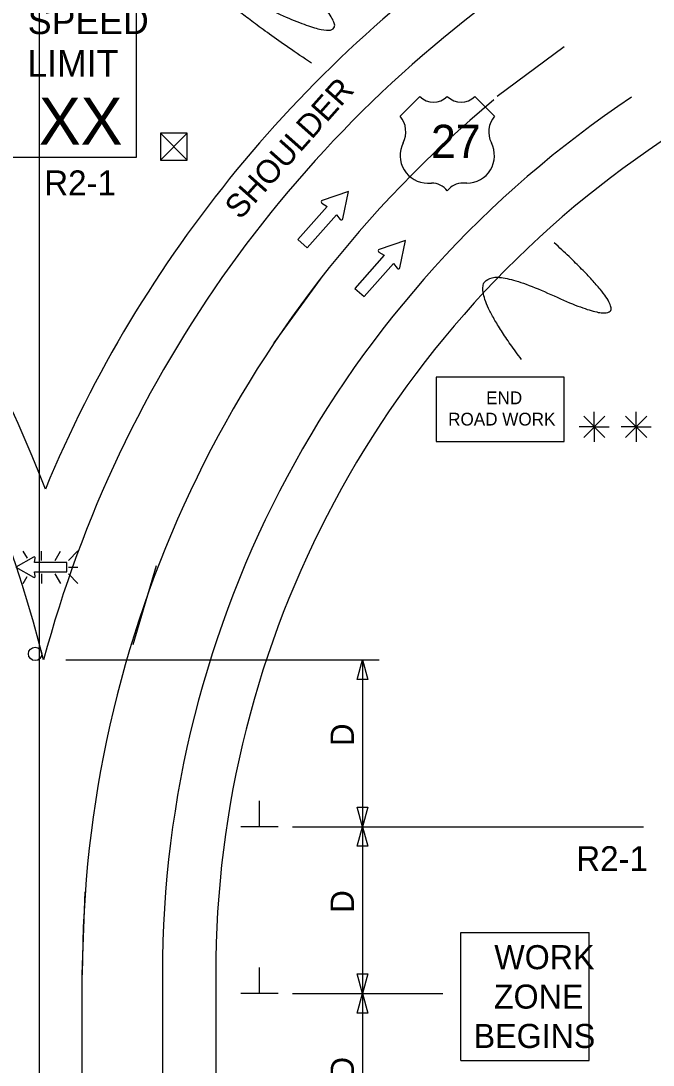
# Model space of a CAD drawing. Extents: x 16303 to 18479, y 5704 to 6974.
# Drawn here: x 16999.2 to 17188.8, y 6497.9 to 6811 of the extents above; entities that cross this region are included whole.
import ezdxf

# ---------------------------------------------------------------- set-up
doc = ezdxf.new("R2010")
doc.units = 0
for name, color, linetype in [('ALI_LEGAL_EX', 7, 'Continuous'), ('MT_SCRATCH_LEVEL_E', 7, 'Continuous'), ('PAVT_EDGE_EX', 7, 'Continuous'), ('TRAFFIC_SIGNS_PR', 7, 'Continuous'), ('TYPICAL_EX', 7, 'Continuous'), ('TYPICAL_TEXT_DIMEN_PR', 7, 'Continuous')]:
    doc.layers.add(name, color=color, linetype=linetype)

msp = doc.modelspace()

# ---------------------------------------------------------------- linework, layer by layer
at = {"layer": 'ALI_LEGAL_EX'}
for p, q in [((17004.68, 6974.12), (17004.68, 6155.98)), ((17004.68, 6877.04), (17004.68, 6013.12)), ((17039.84, 6647.53), (17032.85, 6623.88)), ((17017.65, 6024.8), (17017.65, 6525.15))]:
    msp.add_line(p, q, dxfattribs=at)
for points in [[(17142.04, 6788.34), (17162.08, 6803.27)], [(17075.14, 6714.42), (17089.89, 6734.61)], [(17017.7, 6524.8), (17017.65, 6525.15), (17018.48, 6549.78)]]:
    msp.add_lwpolyline(points, dxfattribs=at)
msp.add_arc((17357.65, 6525.15), 340, 129.5666, 180, dxfattribs=at)
at = {"layer": 'MT_SCRATCH_LEVEL_E'}
for p, q in [((17097.48, 6759.79), (17089.6, 6757.11)), ((17095.77, 6751.62), (17097.48, 6759.79)), ((17091.04, 6755.33), (17082.24, 6745.42)), ((17089.5, 6756.28), (17091.04, 6755.33)), ((17085.03, 6742.93), (17093.84, 6752.84)), ((17093.84, 6752.84), (17094.96, 6751.43)), ((17082.24, 6745.42), (17085.03, 6742.93)), ((17114.56, 6745.13), (17106.68, 6742.45)), ((17112.85, 6736.96), (17114.56, 6745.13)), ((17106.59, 6741.62), (17108.12, 6740.67)), ((17108.12, 6740.67), (17099.32, 6730.76)), ((17102.12, 6728.28), (17110.92, 6738.19)), ((17110.92, 6738.19), (17112.04, 6736.77)), ((17099.32, 6730.76), (17102.12, 6728.28))]:
    msp.add_line(p, q, dxfattribs=at)
for centre, start, end in [((17089.75, 6756.67), 108.8028, 238.3418), ((17095.31, 6751.73), 218.4141, 348.1511), ((17106.84, 6742.01), 108.8028, 238.3418), ((17112.4, 6737.07), 218.4141, 348.1511)]:
    msp.add_arc(centre, 0.463, start, end, dxfattribs=at)
at = {"layer": 'PAVT_EDGE_EX'}
for p, q in [((17041.65, 6525.15), (17041.65, 6062.71)), ((17057.65, 6525.15), (17057.65, 6062.71))]:
    msp.add_line(p, q, dxfattribs=at)
for centre, radius, start, end in [((16629.65, 6525.15), 404, 21.0961, 68.7791), ((16629.65, 6525.15), 388, 14.0482, 68.7791), ((17357.65, 6525.15), 380, 123.6935, 157.5011), ((17357.65, 6525.15), 364, 123.6935, 165.0045), ((17357.65, 6525.15), 316, 123.6935, 180), ((17357.65, 6525.15), 300, 123.6935, 180), ((17357.65, 6525.15), 300, 180, 180.00000277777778)]:
    msp.add_arc(centre, radius, start, end, dxfattribs=at)
at = {"layer": 'TRAFFIC_SIGNS_PR'}
for p, q in [((17033.95, 6770.12), (17033.95, 6818.12)), ((16995.55, 6770.12), (17033.95, 6770.12)), ((17001.2, 6649.83), (16999.94, 6652.01)), ((17005.38, 6649.19), (17005.38, 6652.01)), ((17009.51, 6649.19), (17011.14, 6652.01)), ((17013.47, 6649.19), (17016.29, 6652.02)), ((17013.47, 6647.16), (17016.29, 6647.16)), ((16999.91, 6642.31), (17001.12, 6644.4)), ((17005.38, 6645.13), (17005.38, 6642.31)), ((17011.17, 6642.31), (17009.54, 6645.13)), ((17013.47, 6645.13), (17016.29, 6642.31)), ((17131.18, 6499.25), (17131.18, 6537.65)), ((17131.18, 6537.65), (17169.58, 6537.65)), ((17169.58, 6499.25), (17169.58, 6537.65)), ((17131.18, 6499.25), (17169.58, 6499.25))]:
    msp.add_line(p, q, dxfattribs=at)
msp.add_lwpolyline([(17123.73, 6684.89), (17162.13, 6684.89), (17162.13, 6704.09), (17123.73, 6704.09)], close=True, dxfattribs=at)
for points in [[(17003.05, 6650.18), (16997.74, 6647.16), (17003.05, 6644.12)], [(17003.55, 6644.48), (17003.32, 6645.78), (17013.05, 6645.78), (17013.05, 6648.52), (17003.32, 6648.52), (17003.56, 6649.82)]]:
    msp.add_lwpolyline(points, dxfattribs=at)
msp.add_circle((17003.5, 6621.15), 2, dxfattribs=at)
for centre, start, end in [((17003.22, 6649.88), 350.7308, 118.8916), ((17003.22, 6644.42), 241.4833, 9.9593)]:
    msp.add_arc(centre, 0.341, start, end, dxfattribs=at)
at = {"layer": 'TYPICAL_EX'}
for p, q in [((17112.93, 6782.38), (17118.83, 6788.28)), ((17141.23, 6782.38), (17135.33, 6788.28)), ((17121.17, 6762.32), (17122.35, 6762.32)), ((17132.98, 6762.32), (17131.8, 6762.32))]:
    msp.add_line(p, q, dxfattribs=at)
for centre, radius, start, end in [((17122.95, 6792.57), 5.96, 226.1404, 313.8596), ((17131.21, 6792.57), 5.96, 226.1404, 313.8596), ((17107.34, 6777.66), 7.31, 333.0977, 40.1936), ((17146.82, 6777.66), 7.31, 139.8064, 206.9023), ((17121.19, 6770.57), 8.24, 152.6698, 269.9013), ((17132.97, 6770.57), 8.24, 270.0987, 27.3302), ((17122.37, 6756.42), 5.91, 37.1038, 90.1385), ((17131.79, 6756.42), 5.91, 89.8615, 142.8962)]:
    msp.add_arc(centre, radius, start, end, dxfattribs=at)
at = {"layer": 'TYPICAL_TEXT_DIMEN_PR'}
for p, q in [((17041.08, 6777.24), (17049.08, 6769.24)), ((17041.08, 6769.24), (17049.08, 6777.24)), ((17167.97, 6692.45), (17174.34, 6686.07)), ((17174.34, 6692.45), (17167.97, 6686.07)), ((17171.16, 6689.26), (17171.16, 6693.72)), ((17186.9, 6692.45), (17180.52, 6686.07)), ((17180.53, 6692.45), (17186.9, 6686.07)), ((17183.71, 6689.26), (17183.71, 6693.72)), ((17171.16, 6689.26), (17166.62, 6689.26)), ((17171.16, 6689.26), (17174.34, 6689.26)), ((17171.16, 6689.26), (17175.63, 6689.26)), ((17171.16, 6689.26), (17171.16, 6684.76)), ((17183.71, 6689.26), (17179.18, 6689.26)), ((17183.71, 6689.26), (17186.9, 6689.26)), ((17183.71, 6689.26), (17188.19, 6689.26)), ((17183.71, 6689.26), (17183.71, 6684.76)), ((17012.72, 6619.33), (17106.65, 6619.33)), ((17100.08, 6613.47), (17101.65, 6619.33)), ((17101.65, 6619.33), (17101.65, 6569.33)), ((17101.65, 6619.33), (17103.22, 6613.47)), ((17101.65, 6613.47), (17100.08, 6613.47)), ((17103.22, 6613.47), (17101.65, 6613.47)), ((17070.77, 6569.33), (17070.77, 6577.11)), ((17101.65, 6569.33), (17100.08, 6575.19)), ((17100.08, 6575.19), (17101.65, 6575.19)), ((17101.65, 6575.19), (17103.22, 6575.19)), ((17103.22, 6575.19), (17101.65, 6569.33)), ((17076.4, 6569.33), (17065.15, 6569.33)), ((17080.65, 6569.33), (17185.86, 6569.33)), ((17100.08, 6563.47), (17101.65, 6569.33)), ((17101.65, 6569.33), (17101.65, 6519.33)), ((17101.65, 6569.33), (17103.22, 6563.47)), ((17101.65, 6563.47), (17100.08, 6563.47)), ((17103.22, 6563.47), (17101.65, 6563.47)), ((17070.77, 6519.33), (17070.77, 6527.11)), ((17101.65, 6519.33), (17100.08, 6525.19)), ((17100.08, 6525.19), (17101.65, 6525.19)), ((17101.65, 6525.19), (17103.22, 6525.19)), ((17103.22, 6525.19), (17101.65, 6519.33)), ((17076.4, 6519.33), (17065.15, 6519.33)), ((17080.65, 6519.33), (17125.76, 6519.33)), ((17100.08, 6513.47), (17101.65, 6519.33)), ((17101.65, 6519.33), (17103.22, 6513.47)), ((17101.65, 6519.33), (17101.65, 6469.33)), ((17101.65, 6513.47), (17100.08, 6513.47)), ((17103.22, 6513.47), (17101.65, 6513.47))]:
    msp.add_line(p, q, dxfattribs=at)
msp.add_lwpolyline([(17041.08, 6777.24), (17041.08, 6769.24), (17049.08, 6769.24), (17049.08, 6777.24)], close=True, dxfattribs=at)
for points in [[(17086.35, 6798.24), (17039.53, 6830.07), (17110.85, 6797.33), (17076.24, 6829.21)], [(17149.31, 6709.45), (17122.41, 6745.3), (17193.74, 6712.56), (17159.13, 6744.44)]]:
    msp.add_open_spline(points, degree=2, dxfattribs=at)

# ---------------------------------------------------------------- texts
at = {"layer": 'TRAFFIC_SIGNS_PR'}
for s, height, p in [('SPEED', 8, (17001.31, 6806.98)), ('LIMIT', 8, (17001.15, 6794.18)), ('XX', 14.031, (17004.66, 6773.88)), ('R2-1', 7.44, (17006.22, 6758.68)), ('END', 3.831, (17138.73, 6696.02)), ('ROAD WORK', 3.831, (17127.34, 6689.63)), ('R2-1', 7.44, (17165.72, 6556.06)), ('WORK', 7.217, (17141.18, 6526.62)), ('ZONE', 7.217, (17141.06, 6514.81)), ('BEGINS', 7.217, (17134.99, 6503))]:
    msp.add_text(s, height=height, dxfattribs=at).set_placement(p)
at = {"layer": 'TYPICAL_EX'}
msp.add_text('27', height=10, dxfattribs=at).set_placement((17122.19, 6769.81))
at = {"layer": 'TYPICAL_TEXT_DIMEN_PR'}
for s, rotation, p in [('SHOULDER', 48.378, (17065, 6751.09)), ('D', 90, (17099.09, 6593.55)), ('D', 90, (17099.09, 6543.55)), ('D', 90, (17099.09, 6493.55))]:
    msp.add_text(s, height=7, rotation=rotation, dxfattribs=at).set_placement(p)

doc.saveas('drawing.dxf')
